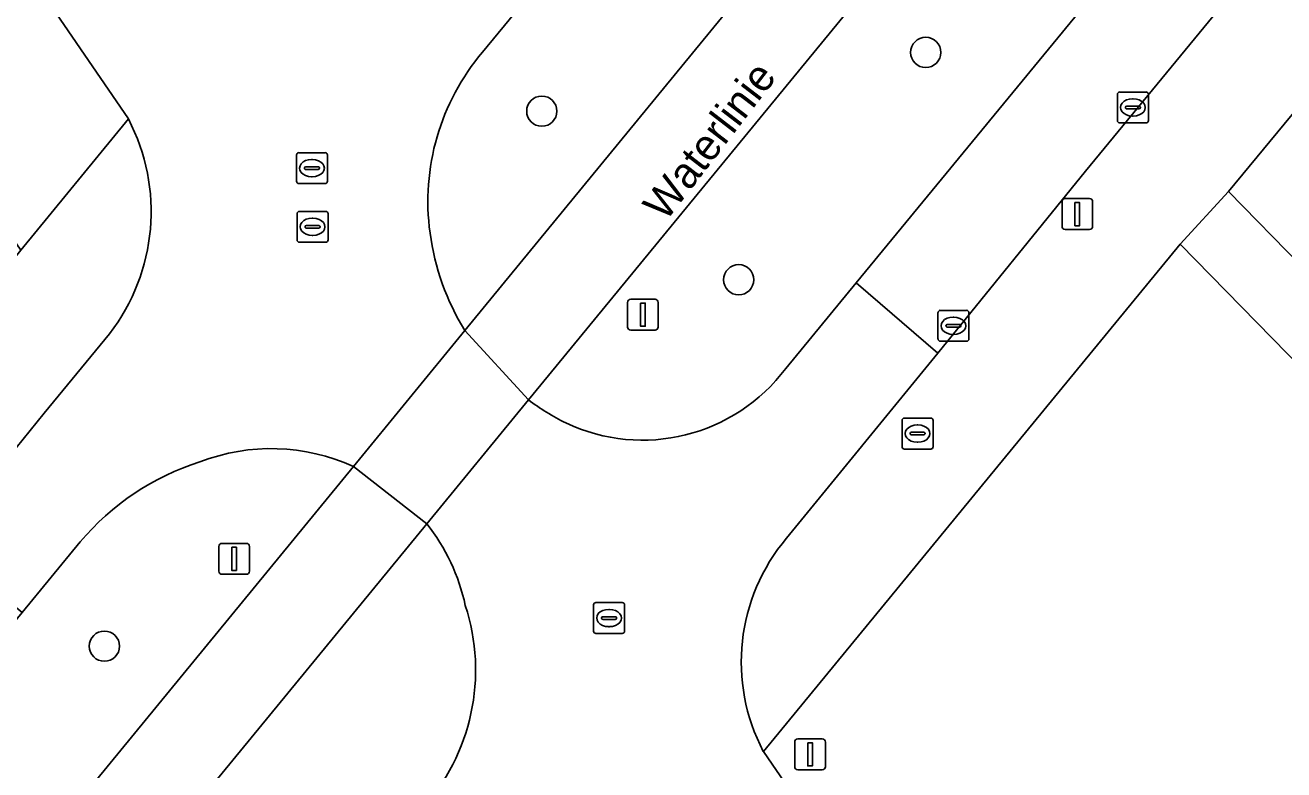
# Model space of a CAD drawing. Extents: x 155275 to 156265, y 382654 to 383635.
# Drawn here: x 155562.17 to 155602.89, y 382967.59 to 382991.69 of the extents above; entities that cross this region are included whole.
import ezdxf

# ---------------------------------------------------------------- set-up
doc = ezdxf.new("R2010")
doc.units = 0
for name, color, linetype in [('IMGEO_Berm_groen', 7, 'Continuous'), ('IMGEO_Boom', 7, 'Continuous'), ('IMGEO_Brandkraan', 7, 'Continuous'), ('IMGEO_Fietspad_gesloten', 7, 'Continuous'), ('IMGEO_Groenvoorziening', 7, 'Continuous'), ('IMGEO_Kolk', 7, 'Continuous'), ('IMGEO_Lichtmast', 7, 'Continuous'), ('IMGEO_Loofbos', 7, 'Continuous'), ('IMGEO_Openbare_ruimte_label', 7, 'Continuous'), ('IMGEO_Rijbaan_lokaal_gesloten', 7, 'Continuous'), ('IMGEO_Rijbaan_lokaal_open', 7, 'Continuous'), ('IMGEO_Rioolput', 7, 'Continuous'), ('IMGEO_Verkeersbordpaal', 7, 'Continuous'), ('IMGEO_Voetpad_open', 7, 'Continuous')]:
    doc.layers.add(name, color=color, linetype=linetype)

msp = doc.modelspace()

# ---------------------------------------------------------------- linework, layer by layer
at = {"layer": 'IMGEO_Berm_groen'}
for points in [[(155644.459, 383064.506), (155661.118, 383084.828), (155693.747, 383124.076), (155702.643, 383134.878), (155706.581, 383139.306), (155703.21, 383144.19), (155580.772, 382995.445), (155576.965, 382990.82)], [(155679.74, 383093.59), (155711.442, 383132.126), (155708.331, 383136.749), (155705.062, 383133.055), (155702.244, 383129.715), (155696.136, 383122.234), (155669.504, 383090.181), (155602.123, 383008.412), (155578.449, 382979.563)], [(155586.774, 382980.583), (155589.051, 382983.35), (155679.74, 383093.59)], [(155576.394, 382981.806), (155599.926, 383010.505), (155644.459, 383064.506)], [(155548.966, 382948.356), (155572.789, 382977.41)], [(155575.161, 382975.555), (155545.301, 382939.168), (155518.802, 382907.088), (155511.334, 382898.215), (155497.335, 382881.332), (155496.67, 382880.437)], [(155563.942, 382974.963), (155562.068, 382972.685), (155509.377, 382908.625), (155490.162, 382885.345)]]:
    msp.add_lwpolyline(points, dxfattribs=at)
for centre, radius, start, end in [((155582.679, 382985.99), 7.482, 139.7934, 187.8847), ((155583.26, 382986.034), 8.064, 187.6253, 211.6226), ((155582.142, 382984.034), 5.776, 244.5799, 323.3144), ((155583.212, 382985.954), 7.971, 233.3012, 243.5575), ((155570.132, 382971.569), 6.417, 65.5437, 111.1126), ((155570.374, 382969.536), 8.415, 107.6581, 139.8447), ((155570.121, 382971.567), 6.427, 12.0274, 38.354), ((155570.032, 382970.816), 6.709, 317.6614, 18.1527)]:
    msp.add_arc(centre, radius, start, end, dxfattribs=at)
at = {"layer": 'IMGEO_Boom'}
for centre in [(155591.307, 382990.81), (155578.883, 382988.909), (155585.255, 382983.451), (155564.731, 382971.59)]:
    msp.add_circle(centre, 0.489, dxfattribs=at)
at = {"layer": 'IMGEO_Brandkraan'}
for p, q in [((155590.54, 382978.046), (155590.54, 382978.898)), ((155590.615, 382978.972), (155591.467, 382978.972)), ((155591.028, 382978.752), (155591.053, 382978.752)), ((155591.541, 382978.898), (155591.541, 382978.046)), ((155590.799, 382978.466), (155590.799, 382978.478)), ((155591.237, 382978.429), (155590.839, 382978.429)), ((155590.842, 382978.515), (155591.24, 382978.515)), ((155591.283, 382978.478), (155591.283, 382978.466)), ((155591.467, 382977.972), (155590.615, 382977.972)), ((155591.051, 382978.192), (155591.026, 382978.192))]:
    msp.add_line(p, q, dxfattribs=at)
for points in [[(155590.54, 382978.046), (155590.54, 382978.898)], [(155590.615, 382978.972), (155591.467, 382978.972)], [(155591.541, 382978.898), (155591.541, 382978.046)], [(155591.467, 382977.972), (155590.615, 382977.972)]]:
    msp.add_lwpolyline(points, dxfattribs=at)
for centre, radius, start, end in [((155590.617, 382978.896), 0.0765, 91.552, 178.448), ((155590.617, 382978.896), 0.0765, 91.552, 178.448), ((155591.465, 382978.896), 0.0765, 1.552, 88.448), ((155591.465, 382978.896), 0.0765, 1.552, 88.448), ((155590.839, 382978.475), 0.0403, 85.8775, 175.7526), ((155590.836, 382978.465), 0.0366, 178.938, 274.7102), ((155591.24, 382978.472), 0.043, 264.8664, 352.4533), ((155591.244, 382978.477), 0.0386, 1.7309, 96.639), ((155590.617, 382978.048), 0.0765, 181.552, 268.448), ((155590.617, 382978.048), 0.0765, 181.552, 268.448), ((155591.465, 382978.048), 0.0765, 271.552, 358.448), ((155591.465, 382978.048), 0.0765, 271.552, 358.448)]:
    msp.add_arc(centre, radius, start, end, dxfattribs=at)
for centre, major_axis, ratio, start_param, end_param in [((155591.027, 382978.472), (-0.387, 0.002), 0.722429, 4.712389, 7.853982), ((155591.052, 382978.472), (-0.39, 0.002), 0.717154, 1.570796, 4.712389)]:
    msp.add_ellipse(centre, major_axis=major_axis, ratio=ratio, start_param=start_param, end_param=end_param, dxfattribs=at)
at = {"layer": 'IMGEO_Fietspad_gesloten'}
for points in [[(155602.123, 383008.412), (155669.504, 383090.181), (155696.136, 383122.234), (155702.244, 383129.715), (155705.062, 383133.055), (155708.331, 383136.749), (155709.688, 383138.266), (155711.139, 383139.825), (155709.446, 383142.395), (155707.929, 383140.815), (155706.581, 383139.306), (155702.643, 383134.878), (155693.747, 383124.076), (155661.118, 383084.828), (155644.459, 383064.506), (155599.926, 383010.505), (155576.394, 382981.806), (155578.449, 382979.563)], [(155578.449, 382979.563), (155576.394, 382981.806), (155572.789, 382977.41), (155575.161, 382975.555)]]:
    msp.add_lwpolyline(points, close=True, dxfattribs=at)
for points in [[(155575.161, 382975.555), (155572.789, 382977.41), (155548.966, 382948.356), (155528.673, 382923.729), (155507.607, 382898.405), (155494.374, 382882.291), (155493.817, 382881.613)], [(155496.244, 382879.863), (155496.67, 382880.437), (155497.335, 382881.332), (155511.334, 382898.215), (155518.802, 382907.088), (155545.301, 382939.168), (155575.161, 382975.555)]]:
    msp.add_lwpolyline(points, dxfattribs=at)
at = {"layer": 'IMGEO_Groenvoorziening'}
for points in [[(155562.266, 382993.404), (155561.072, 382995.153), (155556.72, 382992.177), (155562.024, 382984.409), (155565.506, 382988.657)], [(155607.374, 382987.255), (155605.866, 382988.916), (155604.634, 382990.274), (155604.5, 382990.422), (155601.104, 382986.305), (155605.83, 382981.478), (155609.384, 382984.947)]]:
    msp.add_lwpolyline(points, close=True, dxfattribs=at)
at = {"layer": 'IMGEO_Kolk'}
for p, q in [((155597.508, 382988.603), (155597.508, 382989.455)), ((155597.583, 382989.529), (155598.435, 382989.529)), ((155597.996, 382989.309), (155598.021, 382989.309)), ((155598.509, 382989.455), (155598.509, 382988.603)), ((155597.767, 382989.023), (155597.767, 382989.035)), ((155598.205, 382988.986), (155597.807, 382988.986)), ((155597.81, 382989.072), (155598.208, 382989.072)), ((155598.251, 382989.035), (155598.251, 382989.023)), ((155598.435, 382988.529), (155597.583, 382988.529)), ((155598.019, 382988.749), (155597.994, 382988.749)), ((155591.702, 382981.535), (155591.702, 382982.387)), ((155591.777, 382982.461), (155592.629, 382982.461)), ((155592.703, 382982.387), (155592.703, 382981.535)), ((155591.961, 382981.955), (155591.961, 382981.967)), ((155592.399, 382981.918), (155592.001, 382981.918)), ((155592.004, 382982.004), (155592.402, 382982.004)), ((155592.19, 382982.241), (155592.215, 382982.241)), ((155592.445, 382981.967), (155592.445, 382981.955)), ((155592.213, 382981.681), (155592.188, 382981.681)), ((155592.629, 382981.461), (155591.777, 382981.461))]:
    msp.add_line(p, q, dxfattribs=at)
for points in [[(155597.508, 382988.603), (155597.508, 382989.455)], [(155597.583, 382989.529), (155598.435, 382989.529)], [(155598.509, 382989.455), (155598.509, 382988.603)], [(155598.435, 382988.529), (155597.583, 382988.529)], [(155591.702, 382981.535), (155591.702, 382982.387)], [(155591.777, 382982.461), (155592.629, 382982.461)], [(155592.703, 382982.387), (155592.703, 382981.535)], [(155592.629, 382981.461), (155591.777, 382981.461)]]:
    msp.add_lwpolyline(points, dxfattribs=at)
for centre, radius, start, end in [((155597.585, 382989.453), 0.0765, 91.552, 178.448), ((155597.585, 382989.453), 0.0765, 91.552, 178.448), ((155598.433, 382989.453), 0.0765, 1.552, 88.448), ((155598.433, 382989.453), 0.0765, 1.552, 88.448), ((155597.807, 382989.032), 0.0403, 85.8775, 175.7526), ((155597.804, 382989.022), 0.0366, 178.938, 274.7102), ((155598.208, 382989.029), 0.043, 264.8664, 352.4533), ((155598.212, 382989.034), 0.0386, 1.7309, 96.639), ((155597.585, 382988.605), 0.0765, 181.552, 268.448), ((155597.585, 382988.605), 0.0765, 181.552, 268.448), ((155598.433, 382988.605), 0.0765, 271.552, 358.448), ((155598.433, 382988.605), 0.0765, 271.552, 358.448), ((155591.779, 382982.385), 0.0765, 91.552, 178.448), ((155591.779, 382982.385), 0.0765, 91.552, 178.448), ((155592.627, 382982.385), 0.0765, 1.552, 88.448), ((155592.627, 382982.385), 0.0765, 1.552, 88.448), ((155592.001, 382981.964), 0.0403, 85.8775, 175.7526), ((155591.998, 382981.954), 0.0366, 178.938, 274.7102), ((155592.402, 382981.961), 0.043, 264.8664, 352.4533), ((155592.406, 382981.966), 0.0386, 1.7309, 96.639), ((155591.779, 382981.537), 0.0765, 181.552, 268.448), ((155591.779, 382981.537), 0.0765, 181.552, 268.448), ((155592.627, 382981.537), 0.0765, 271.552, 358.448), ((155592.627, 382981.537), 0.0765, 271.552, 358.448)]:
    msp.add_arc(centre, radius, start, end, dxfattribs=at)
for centre, major_axis, ratio, start_param, end_param in [((155597.995, 382989.029), (-0.387, 0.002), 0.722429, 4.712389, 7.853982), ((155598.02, 382989.029), (-0.39, 0.002), 0.717154, 1.570796, 4.712389), ((155592.189, 382981.961), (-0.387, 0.002), 0.722429, 4.712389, 7.853982), ((155592.214, 382981.961), (-0.39, 0.002), 0.717154, 1.570796, 4.712389)]:
    msp.add_ellipse(centre, major_axis=major_axis, ratio=ratio, start_param=start_param, end_param=end_param, dxfattribs=at)
at = {"layer": 'IMGEO_Lichtmast'}
for p, q in [((155595.815, 382986.077), (155596.605, 382986.077)), ((155596.605, 382986.077), (155595.815, 382986.077)), ((155595.715, 382985.177), (155595.715, 382985.977)), ((155595.715, 382985.977), (155595.715, 382985.177)), ((155596.705, 382985.977), (155596.705, 382985.177)), ((155596.705, 382985.177), (155596.705, 382985.977)), ((155596.605, 382985.077), (155595.815, 382985.077)), ((155595.815, 382985.077), (155596.605, 382985.077)), ((155587.067, 382967.686), (155587.067, 382968.486)), ((155587.067, 382968.486), (155587.067, 382967.686)), ((155587.167, 382968.586), (155587.957, 382968.586)), ((155587.957, 382968.586), (155587.167, 382968.586)), ((155588.057, 382968.486), (155588.057, 382967.686)), ((155588.057, 382967.686), (155588.057, 382968.486)), ((155587.957, 382967.586), (155587.167, 382967.586)), ((155587.167, 382967.586), (155587.957, 382967.586))]:
    msp.add_line(p, q, dxfattribs=at)
for points in [[(155596.135, 382985.952), (155596.285, 382985.952), (155596.285, 382985.202), (155596.135, 382985.202), (155596.135, 382985.952)], [(155587.487, 382968.461), (155587.637, 382968.461), (155587.637, 382967.711), (155587.487, 382967.711), (155587.487, 382968.461)]]:
    msp.add_lwpolyline(points, dxfattribs=at)
for centre, start, end in [((155595.815, 382985.977), 90, 180), ((155595.815, 382985.977), 90, 180), ((155596.605, 382985.977), 0, 90), ((155596.605, 382985.977), 360, 90), ((155595.815, 382985.177), 180, 270), ((155595.815, 382985.177), 180, 270), ((155596.605, 382985.177), 270, 0), ((155596.605, 382985.177), 270, 0), ((155587.167, 382968.486), 90, 180), ((155587.167, 382968.486), 90, 180), ((155587.957, 382968.486), 0, 90), ((155587.957, 382968.486), 360, 90), ((155587.167, 382967.686), 180, 270), ((155587.167, 382967.686), 180, 270), ((155587.957, 382967.686), 270, 0), ((155587.957, 382967.686), 270, 0)]:
    msp.add_arc(centre, 0.1, start, end, dxfattribs=at)
at = {"layer": 'IMGEO_Loofbos'}
msp.add_lwpolyline([(155608.469, 382975.471), (155599.543, 382984.601), (155586.051, 382968.185), (155586.875, 382966.986), (155588.307, 382964.774), (155588.557, 382964.387), (155592.183, 382964.261), (155606.673, 382942.869)], dxfattribs=at)
at = {"layer": 'IMGEO_Rijbaan_lokaal_gesloten'}
msp.add_lwpolyline([(155712.754, 383133.721), (155711.442, 383132.126), (155679.74, 383093.59), (155589.051, 382983.35), (155591.698, 382981.075), (155596.474, 382986.965), (155631.252, 383029.213), (155635.105, 383033.893), (155643.042, 383043.534), (155646.823, 383048.128), (155682.427, 383091.379)], dxfattribs=at)
at = {"layer": 'IMGEO_Rijbaan_lokaal_open'}
for points in [[(155576.965, 382990.82), (155580.772, 382995.445), (155578.114, 382997.717), (155577.605, 382997.112), (155575.298, 382994.352)], [(155567.246, 382995.751), (155566.772, 382996.446), (155566.438, 382996.221), (155562.266, 382993.404), (155565.506, 382988.657)], [(155586.805, 382975.087), (155591.698, 382981.075), (155589.051, 382983.35), (155586.774, 382980.583)], [(155564.897, 382981.702), (155562.779, 382979.129), (155559.373, 382974.92), (155562.068, 382972.685), (155563.942, 382974.963)], [(155572.789, 382977.41), (155576.394, 382981.806)], [(155578.449, 382979.563), (155575.161, 382975.555)], [(155583.853, 382961.92), (155588.307, 382964.774), (155586.875, 382966.986), (155586.051, 382968.185)]]:
    msp.add_lwpolyline(points, dxfattribs=at)
for centre, radius, start, end in [((155582.679, 382985.99), 7.482, 139.7934, 187.8847), ((155559.756, 382985.656), 6.486, 322.4339, 27.5577), ((155583.26, 382986.034), 8.064, 187.6253, 211.6226), ((155582.142, 382984.034), 5.776, 244.5799, 323.3144), ((155583.212, 382985.954), 7.971, 233.3012, 243.5575), ((155570.132, 382971.569), 6.417, 65.5437, 111.1126), ((155570.374, 382969.536), 8.415, 107.6581, 139.8447), ((155570.121, 382971.567), 6.427, 12.0274, 38.354), ((155591.55, 382971.076), 6.213, 139.7949, 207.7361), ((155570.032, 382970.816), 6.709, 317.6614, 18.1527)]:
    msp.add_arc(centre, radius, start, end, dxfattribs=at)
at = {"layer": 'IMGEO_Rioolput'}
for p, q in [((155570.946, 382986.639), (155570.946, 382987.491)), ((155571.021, 382987.565), (155571.873, 382987.565)), ((155571.434, 382987.345), (155571.459, 382987.345)), ((155571.947, 382987.491), (155571.947, 382986.639)), ((155571.205, 382987.059), (155571.205, 382987.071)), ((155571.643, 382987.022), (155571.245, 382987.022)), ((155571.248, 382987.108), (155571.646, 382987.108)), ((155571.689, 382987.071), (155571.689, 382987.059)), ((155571.873, 382986.565), (155571.021, 382986.565)), ((155571.457, 382986.785), (155571.432, 382986.785)), ((155570.966, 382984.739), (155570.966, 382985.591)), ((155571.041, 382985.665), (155571.893, 382985.665)), ((155571.967, 382985.591), (155571.967, 382984.739)), ((155571.225, 382985.159), (155571.225, 382985.171)), ((155571.268, 382985.208), (155571.666, 382985.208)), ((155571.454, 382985.445), (155571.479, 382985.445)), ((155571.709, 382985.171), (155571.709, 382985.159)), ((155571.663, 382985.122), (155571.265, 382985.122)), ((155571.477, 382984.885), (155571.452, 382984.885)), ((155571.893, 382984.665), (155571.041, 382984.665)), ((155580.634, 382973.001), (155581.486, 382973.001)), ((155580.559, 382972.075), (155580.559, 382972.927)), ((155580.861, 382972.544), (155581.259, 382972.544)), ((155581.047, 382972.781), (155581.072, 382972.781)), ((155581.56, 382972.927), (155581.56, 382972.075)), ((155580.818, 382972.495), (155580.818, 382972.507)), ((155581.256, 382972.458), (155580.858, 382972.458)), ((155581.07, 382972.221), (155581.045, 382972.221)), ((155581.302, 382972.507), (155581.302, 382972.495)), ((155581.486, 382972.001), (155580.634, 382972.001))]:
    msp.add_line(p, q, dxfattribs=at)
for points in [[(155570.946, 382986.639), (155570.946, 382987.491)], [(155571.021, 382987.565), (155571.873, 382987.565)], [(155571.947, 382987.491), (155571.947, 382986.639)], [(155571.873, 382986.565), (155571.021, 382986.565)], [(155570.966, 382984.739), (155570.966, 382985.591)], [(155571.041, 382985.665), (155571.893, 382985.665)], [(155571.967, 382985.591), (155571.967, 382984.739)], [(155571.893, 382984.665), (155571.041, 382984.665)], [(155580.634, 382973.001), (155581.486, 382973.001)], [(155580.559, 382972.075), (155580.559, 382972.927)], [(155581.56, 382972.927), (155581.56, 382972.075)], [(155581.486, 382972.001), (155580.634, 382972.001)]]:
    msp.add_lwpolyline(points, dxfattribs=at)
for centre, radius, start, end in [((155571.023, 382987.489), 0.0765, 91.552, 178.448), ((155571.023, 382987.489), 0.0765, 91.552, 178.448), ((155571.871, 382987.489), 0.0765, 1.552, 88.448), ((155571.871, 382987.489), 0.0765, 1.552, 88.448), ((155571.245, 382987.068), 0.0403, 85.8775, 175.7526), ((155571.242, 382987.058), 0.0366, 178.938, 274.7102), ((155571.646, 382987.065), 0.043, 264.8664, 352.4533), ((155571.65, 382987.07), 0.0386, 1.7309, 96.639), ((155571.023, 382986.641), 0.0765, 181.552, 268.448), ((155571.023, 382986.641), 0.0765, 181.552, 268.448), ((155571.871, 382986.641), 0.0765, 271.552, 358.448), ((155571.871, 382986.641), 0.0765, 271.552, 358.448), ((155571.043, 382985.589), 0.0765, 91.552, 178.448), ((155571.043, 382985.589), 0.0765, 91.552, 178.448), ((155571.891, 382985.589), 0.0765, 1.552, 88.448), ((155571.891, 382985.589), 0.0765, 1.552, 88.448), ((155571.265, 382985.168), 0.0403, 85.8775, 175.7526), ((155571.67, 382985.17), 0.0386, 1.7309, 96.639), ((155571.262, 382985.158), 0.0366, 178.938, 274.7102), ((155571.666, 382985.165), 0.043, 264.8664, 352.4533), ((155571.043, 382984.741), 0.0765, 181.552, 268.448), ((155571.043, 382984.741), 0.0765, 181.552, 268.448), ((155571.891, 382984.741), 0.0765, 271.552, 358.448), ((155571.891, 382984.741), 0.0765, 271.552, 358.448), ((155580.636, 382972.925), 0.0765, 91.552, 178.448), ((155580.636, 382972.925), 0.0765, 91.552, 178.448), ((155581.484, 382972.925), 0.0765, 1.552, 88.448), ((155581.484, 382972.925), 0.0765, 1.552, 88.448), ((155580.858, 382972.504), 0.0403, 85.8775, 175.7526), ((155581.263, 382972.506), 0.0386, 1.7309, 96.639), ((155580.855, 382972.494), 0.0366, 178.938, 274.7102), ((155581.259, 382972.501), 0.043, 264.8664, 352.4533), ((155580.636, 382972.077), 0.0765, 181.552, 268.448), ((155580.636, 382972.077), 0.0765, 181.552, 268.448), ((155581.484, 382972.077), 0.0765, 271.552, 358.448), ((155581.484, 382972.077), 0.0765, 271.552, 358.448)]:
    msp.add_arc(centre, radius, start, end, dxfattribs=at)
for centre, major_axis, ratio, start_param, end_param in [((155571.433, 382987.065), (-0.387, 0.002), 0.722429, 4.712389, 7.853982), ((155571.458, 382987.065), (-0.39, 0.002), 0.717154, 1.570796, 4.712389), ((155571.453, 382985.165), (-0.387, 0.002), 0.722429, 4.712389, 7.853982), ((155571.478, 382985.165), (-0.39, 0.002), 0.717154, 1.570796, 4.712389), ((155581.046, 382972.501), (-0.387, 0.002), 0.722429, 4.712389, 7.853982), ((155581.071, 382972.501), (-0.39, 0.002), 0.717154, 1.570796, 4.712389)]:
    msp.add_ellipse(centre, major_axis=major_axis, ratio=ratio, start_param=start_param, end_param=end_param, dxfattribs=at)
at = {"layer": 'IMGEO_Verkeersbordpaal'}
for p, q in [((155581.759, 382982.819), (155582.549, 382982.819)), ((155582.549, 382982.819), (155581.759, 382982.819)), ((155581.659, 382981.919), (155581.659, 382982.719)), ((155581.659, 382982.719), (155581.659, 382981.919)), ((155582.649, 382982.719), (155582.649, 382981.919)), ((155582.649, 382981.919), (155582.649, 382982.719)), ((155582.549, 382981.819), (155581.759, 382981.819)), ((155581.759, 382981.819), (155582.549, 382981.819)), ((155568.432, 382974.017), (155568.432, 382974.817)), ((155568.432, 382974.817), (155568.432, 382974.017)), ((155568.532, 382974.917), (155569.322, 382974.917)), ((155569.322, 382974.917), (155568.532, 382974.917)), ((155569.422, 382974.817), (155569.422, 382974.017)), ((155569.422, 382974.017), (155569.422, 382974.817)), ((155569.322, 382973.917), (155568.532, 382973.917)), ((155568.532, 382973.917), (155569.322, 382973.917))]:
    msp.add_line(p, q, dxfattribs=at)
for points in [[(155582.079, 382982.694), (155582.229, 382982.694), (155582.229, 382981.944), (155582.079, 382981.944), (155582.079, 382982.694)], [(155568.852, 382974.792), (155569.002, 382974.792), (155569.002, 382974.042), (155568.852, 382974.042), (155568.852, 382974.792)]]:
    msp.add_lwpolyline(points, dxfattribs=at)
for centre, start, end in [((155581.759, 382982.719), 90, 180), ((155581.759, 382982.719), 90, 180), ((155582.549, 382982.719), 0, 90), ((155582.549, 382982.719), 360, 90), ((155581.759, 382981.919), 180, 270), ((155581.759, 382981.919), 180, 270), ((155582.549, 382981.919), 270, 0), ((155582.549, 382981.919), 270, 0), ((155568.532, 382974.817), 90, 180), ((155568.532, 382974.817), 90, 180), ((155569.322, 382974.817), 0, 90), ((155569.322, 382974.817), 360, 90), ((155568.532, 382974.017), 180, 270), ((155568.532, 382974.017), 180, 270), ((155569.322, 382974.017), 270, 0), ((155569.322, 382974.017), 270, 0)]:
    msp.add_arc(centre, 0.1, start, end, dxfattribs=at)
at = {"layer": 'IMGEO_Voetpad_open'}
for points in [[(155708.323, 383122.836), (155682.427, 383091.379), (155646.823, 383048.128), (155643.042, 383043.534), (155635.105, 383033.893), (155631.252, 383029.213), (155596.474, 382986.965), (155591.698, 382981.075), (155586.805, 382975.087)], [(155586.051, 382968.185), (155599.543, 382984.601), (155601.104, 382986.305), (155604.5, 382990.422), (155616.181, 383004.585), (155622.291, 383012.029), (155626.227, 383016.819), (155634.326, 383026.663), (155638.127, 383031.274), (155639.004, 383032.339), (155641.208, 383035.014)], [(155565.506, 382988.657), (155562.024, 382984.409), (155560.718, 382982.8), (155559.286, 382981.036), (155559.216, 382980.95), (155556.539, 382977.694), (155551.924, 382972.117), (155545.952, 382964.868), (155542.339, 382960.486), (155519.289, 382932.53), (155516.414, 382928.987), (155497.755, 382906.335), (155493.084, 382900.658), (155487.457, 382893.827), (155486.483, 382892.646), (155485.973, 382892.026), (155484.389, 382890.104), (155483.002, 382888.419)], [(155609.206, 382978.006), (155607.182, 382980.056), (155610.761, 382983.522), (155609.384, 382984.947), (155605.83, 382981.478), (155601.104, 382986.305), (155599.543, 382984.601), (155608.469, 382975.471)], [(155559.373, 382974.92), (155562.779, 382979.129), (155564.897, 382981.702)]]:
    msp.add_lwpolyline(points, dxfattribs=at)
for centre, radius, start, end in [((155559.756, 382985.656), 6.486, 322.4339, 27.5577), ((155591.55, 382971.076), 6.213, 139.7949, 207.7361)]:
    msp.add_arc(centre, radius, start, end, dxfattribs=at)

# ---------------------------------------------------------------- texts
at = {"layer": 'IMGEO_Openbare_ruimte_label'}
msp.add_text('Waterlinie', height=1, rotation=52.3965, dxfattribs=at).set_placement((155582.885, 382985.301))
msp.add_text('Waterlinie', height=1, rotation=52.3965, dxfattribs=at).set_placement((155582.885, 382985.301))

doc.saveas('drawing.dxf')
